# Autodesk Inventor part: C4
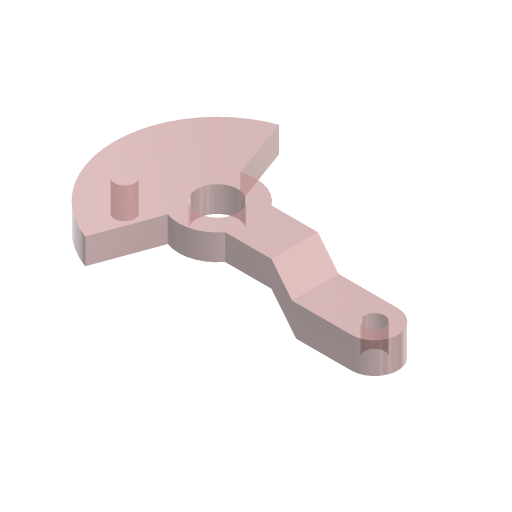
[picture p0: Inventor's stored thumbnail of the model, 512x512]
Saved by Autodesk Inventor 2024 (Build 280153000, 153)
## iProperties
Company: ATC
Shininess: 20.0
Angle Display Precision: 2
Document Length Units: 11269
Document Angle Units: 11279
Document Time Units: 11290
Document Mass Units: 11283
Document Length Units Precision: 3
Document Angle Units Precision: 2
Created: 2023-03
Part Number: C4
Material: Kurs-AJ
Document SubType Name: Modelowanie
Designer: Andrzej Jaskulski
Density: 1 g/cm^3
Appearance: Jasnoczerwone
Checked By: A.J.
Engr Approved By: Andrzej Jaskulski
Mfg Approved By: Andrzej Jaskulski
Authority: A.J.
Density: 0.0
Volumn: 0.0
Area: 0.0
PropertySet Name: Model Information
Control State: 0
Master: False
Checked Out: False
Title: A.J.: Kurs R2024-MEP
Author: Andrzej Jaskulski
Revision Number: 1/24
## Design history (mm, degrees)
node "Bryła1"
node "Korpusy bryłowe"
node "Korpusy powierzchniowe"
node "Początek"
sketch "Szkic1"
  geometry: L1 (36.371, 18.985)-(54.371, 18.985); L2 (36.371, 0.985)-(54.371, 0.985); L3 (19.241, -4.11)-(10.691, -27.603); L4 (19.241, 24.081)-(10.691, 47.573); L5 (-41.915, 9.985)-(91.63, 9.985); L6 (54.371, 0.985)-(54.371, 18.985); L7 (19.241, -4.11)-(24.371, 9.985); L8 (19.241, 24.081)-(24.371, 9.985); C1 r 8 at (24.371, 9.985); C2 r 4 at (-11.629, 9.985); A1 r 15 centre (24.371, 9.985) between (19.241, 24.081) and (19.241, -4.11); A2 r 40 centre (24.371, 9.985) between (10.691, 47.573) and (10.691, -27.603)
  constraints: 16 end point, 6 point on circle, 4 centre point, 2 collinear, 2 point on line, 1 coincident, 1 concentric, 1 horizontal, 1 parallel, 1 perpendicular, 1 tangent, 3 other
  dimensions: "d4" = 40 radius of A2; "d5" = 30 diameter of A1; "d6" = 16 diameter of C1; "d7" = 8 diameter of C2; "d22" = 140 deg angle of L3 L4; "d23" = 30 distance from line of L6 C1.centre; "d24" = 18 distance of L2.end L1.end
extrude "Wyciągnięcie proste1" new body sketch "Szkic1" distance "d2" = 10; taper "d3" = 0 deg
extrude "Wyciągnięcie proste2" join sketch "Szkic1" distance "d8" = 12; taper "d9" = 0 deg
extrude "Wyciągnięcie proste3" cut sketch "Szkic1" extent not by distance; stored distance "d12" = 12; taper "d13" = 0 deg
node "Oś konstrukcyjna1"
node "Płaszczyzna konstrukcyjna2"
sketch "Szkic5"
  geometry: L1 (30, 0)-(30, 10) reference; L2 (30, 10)-(38, 0); L3 (38, 0)-(70, 0); L4 (70, 0)-(70, -12); L5 (70, -12)-(39.6, -12); L6 (39.6, -12)-(30, 0); L7 (0, -16.4)-(0, 14.4) reference
  constraints: 10 end point, 3 perpendicular, 1 parallel, 1 point on line
  dimensions: "d19" = 12 distance between parallel lines of L3 L5; "d20" = 38 distance from line of L2.end L7; "d28" = 70 distance between parallel lines of L4 L7
extrude "Wyciągnięcie proste5" join sketch "Szkic5" stored distance "d25" = 17.57962; taper "d26" = 0 deg
fillet "Zaokrąglenie1" dims "d27" = 9
sketch "Szkic6"
  geometry: A1 r 9 centre (23, 9) between (23, 0) and (23, 18) reference; 1 further point
hole "Otwór1" sketch "Szkic6" diameter "d30" = 8; stored, may be unused: countersink angle "d34" = 82 deg, drill point angle "d36" = 118 deg; dims "d31" = 6, "d32" = 4, "d33" = 2, "d35" = 8
node "Płaszczyzna YZ"
node "Płaszczyzna XZ"
node "Płaszczyzna XY"
node "Oś X"
node "Oś Y"
node "Oś Z"
node "Punkt środkowy"
other parameters: "d0" = 110 deg, "d18" = 0
